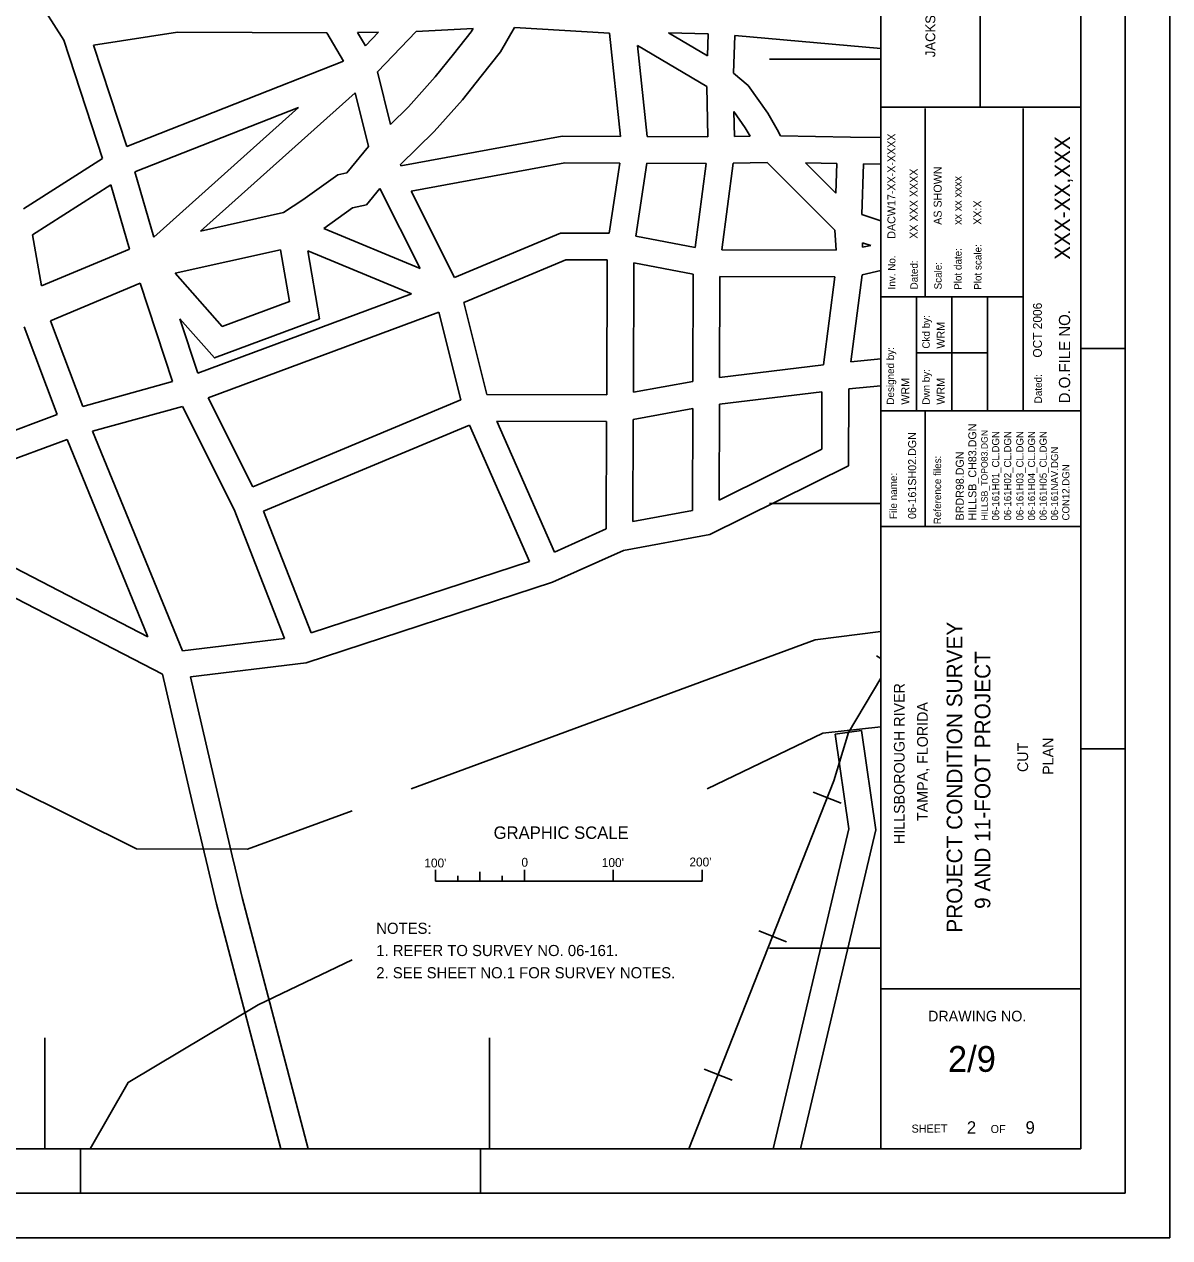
# Model space of a CAD drawing. Extents: x 503330 to 511530, y 1310349 to 1316149.
# Drawn here: x 508954 to 511530, y 1310349 to 1313078 of the extents above; entities that cross this region are included whole.
import ezdxf

# ---------------------------------------------------------------- set-up
doc = ezdxf.new("R2010")
doc.units = 0
for name, color, linetype in [('G-ANNO-TEXT', 7, 'Continuous'), ('G-ANNO-TTLB', 7, 'Continuous'), ('Level 1', 7, 'Continuous'), ('Level 2', 7, 'Continuous'), ('Level 23', 7, 'Continuous'), ('Level 32', 7, 'Continuous'), ('Level 37', 7, 'Continuous'), ('Level 5', 7, 'Continuous'), ('Level 6', 7, 'Continuous')]:
    doc.layers.add(name, color=color, linetype=linetype)

msp = doc.modelspace()

# ---------------------------------------------------------------- linework, layer by layer
at = {"layer": 'G-ANNO-TTLB'}
for p, q in [((511430.3, 1310448.5), (511430.3, 1316048.5)), ((510880.3, 1310548.5), (510880.3, 1315948.5)), ((511330.3, 1315948.5), (511330.3, 1310548.5)), ((511103.7, 1313931.1), (511103.7, 1312891.3)), ((511330.3, 1312891.3), (510880.3, 1312891.3)), ((510979.9, 1312888.5), (510979.9, 1312464.7)), ((511200.7, 1312888.5), (511200.7, 1312208.5)), ((511200.7, 1312464.7), (510880.3, 1312464.7)), ((510960.5, 1312464.7), (510960.5, 1312208.5)), ((511040.3, 1312464.7), (511040.3, 1312208.5)), ((511120.7, 1312464.7), (511120.7, 1312208.5)), ((511430.3, 1312348.5), (511330.3, 1312348.5)), ((511120.7, 1312338.9), (510960.5, 1312338.9)), ((511330.3, 1312208.5), (510880.3, 1312208.5)), ((510979.9, 1312208.5), (510979.9, 1311948.3)), ((511330.3, 1311948.3), (510880.3, 1311948.3)), ((511430.3, 1311448.5), (511330.3, 1311448.5)), ((511330.3, 1310908.5), (510880.3, 1310908.5)), ((511330.3, 1310548.5), (503680.3, 1310548.5)), ((509080.3, 1310448.5), (509080.3, 1310548.5)), ((509980.3, 1310448.5), (509980.3, 1310548.5)), ((503430.3, 1310448.5), (511430.3, 1310448.5))]:
    msp.add_line(p, q, dxfattribs=at)
for points in [[(503330.3, 1310348.5), (511530.3, 1310348.5), (511530.3, 1316148.5), (503330.3, 1316148.5)], [(503330.3, 1310348.5), (511530.3, 1310348.5), (511530.3, 1316148.5), (503330.3, 1316148.5)], [(503330.3, 1316148.5), (511530.3, 1316148.5), (511530.3, 1310348.5), (503330.3, 1310348.5)]]:
    msp.add_lwpolyline(points, close=True, dxfattribs=at)
msp.add_lwpolyline([(511480.3, 1310348.5), (511530.3, 1310348.5), (511530.3, 1310398.5)], dxfattribs=at)
at = {"layer": 'Level 1'}
for p, q in [((509878.7, 1311150.9), (509878.7, 1311176)), ((509978.7, 1311150.9), (509978.7, 1311171.4)), ((510078.7, 1311150.9), (510078.7, 1311176)), ((510078.7, 1311150.9), (510078.7, 1311176)), ((510278.7, 1311150.9), (510278.7, 1311176)), ((510478.7, 1311150.9), (510478.7, 1311176)), ((509878.7, 1311150.9), (510478.7, 1311150.9)), ((509928.7, 1311151.4), (509928.7, 1311162.9)), ((509978.7, 1311151.4), (509978.7, 1311162.9)), ((510028.7, 1311151.4), (510028.7, 1311162.9)), ((510078.7, 1311150.9), (510078.7, 1311162.9))]:
    msp.add_line(p, q, dxfattribs=at)
at = {"layer": 'Level 2'}
for p, q in [((510630.3, 1313000), (510880.3, 1313000)), ((510630.3, 1312000), (510880.3, 1312000)), ((510630.3, 1311000), (510880.3, 1311000)), ((509000, 1310548.5), (509000, 1310798.5)), ((510000, 1310548.5), (510000, 1310798.5))]:
    msp.add_line(p, q, dxfattribs=at)
at = {"layer": 'Level 23'}
for p, q in [((509350.1, 1312613.1), (509536.7, 1312654.4)), ((508992.1, 1312489.6), (509190.3, 1312572.4)), ((509293.1, 1312518.5), (509530.1, 1312571)), ((509012.5, 1312411.4), (509214.2, 1312495.7))]:
    msp.add_line(p, q, dxfattribs=at)
for points in [[(509777.5, 1312852.8), (509817.7, 1312892.2), (509878.3, 1312959.9), (509919.1, 1313011.2), (509958.7, 1313060.9), (509963.2, 1313068.8)], [(509800.1, 1312763), (509875.6, 1312836.8), (509939.5, 1312908.3), (509981.7, 1312961.4), (510025.2, 1313016), (510056.3, 1313070.6)], [(509536.7, 1312654.4), (509580.4, 1312683.1), (509658.9, 1312739.5), (509679.4, 1312744.1), (509728, 1312802.9)], [(509627.4, 1312618.4), (509692.2, 1312665), (509723.5, 1312671.9), (509753.8, 1312708.5)]]:
    msp.add_lwpolyline(points, dxfattribs=at)
at = {"layer": 'Level 32'}
for p, q in [((508895.9, 1313275.2), (509042.6, 1313042.1)), ((509109.4, 1313030.8), (509298.3, 1313060.5)), ((509298.3, 1313060.5), (509634, 1313059.2)), ((509634, 1313059.2), (509671.7, 1312994.9)), ((509703.2, 1313059.9), (509750.7, 1313060.5)), ((509703.2, 1313059.9), (509721.1, 1313029.4)), ((509750.7, 1313060.5), (509721.1, 1313029.4)), ((509835.2, 1313062.1), (509748.4, 1312971.1)), ((509835.2, 1313062.1), (509963.2, 1313068.8)), ((510056.3, 1313070.6), (510269.8, 1313058.3)), ((510269.8, 1313058.3), (510294.7, 1312825.9)), ((510403.1, 1313058.6), (510490.3, 1313006.8)), ((510403.1, 1313058.6), (510491.9, 1313056.6)), ((510491.9, 1313056.6), (510490.3, 1313006.8)), ((509042.6, 1313042.1), (509129.9, 1312776.5)), ((509109.4, 1313030.8), (509184.3, 1312803.3)), ((510333.1, 1313030.4), (510355.1, 1312825.7)), ((510333.1, 1313030.4), (510488.9, 1312937.8)), ((510551.9, 1313053.2), (510549, 1312968.5)), ((510551.9, 1313053.2), (510880.3, 1313023.5)), ((509184.3, 1312803.3), (509671.7, 1312994.9)), ((509748.4, 1312971.1), (509777.5, 1312852.8)), ((509698.2, 1312924.2), (509350.1, 1312613.1)), ((509698.2, 1312924.2), (509728, 1312802.9)), ((510488.9, 1312937.8), (510491.2, 1312825.2)), ((509202.2, 1312745.9), (509570.7, 1312890.8)), ((509570.7, 1312890.8), (509244.9, 1312599.5)), ((510550.1, 1312881.7), (510551.2, 1312825.7)), ((510355.1, 1312825.7), (510491.2, 1312825.2)), ((510551.2, 1312825.7), (510586.8, 1312826.5)), ((510655.1, 1312827.2), (510812.5, 1312824)), ((510812.5, 1312824), (510880.3, 1312823.8)), ((508951.9, 1312662.9), (509129.9, 1312776.5)), ((509800.1, 1312763), (509800.9, 1312759.7)), ((510293.3, 1312765.9), (510269.3, 1312607.9)), ((510353.9, 1312765.7), (510329, 1312601.8)), ((510353.9, 1312765.7), (510487.7, 1312765.2)), ((510487.7, 1312765.2), (510463, 1312576.2)), ((510548.3, 1312765.7), (510522.8, 1312570.6)), ((510548.3, 1312765.7), (510624.7, 1312767.3)), ((510624.7, 1312767.3), (510777.3, 1312615.2)), ((510710.9, 1312766.1), (510779.1, 1312698.1)), ((510710.9, 1312766.1), (510781.4, 1312764.7)), ((510781.4, 1312764.7), (510779.1, 1312698.1)), ((510841.4, 1312763.9), (510837.4, 1312650)), ((510841.4, 1312763.9), (510880.3, 1312763.8)), ((509202.2, 1312745.9), (509244.9, 1312599.5)), ((508972.1, 1312604.6), (509148.1, 1312717)), ((509148.1, 1312717), (509190.3, 1312572.4)), ((509753.8, 1312708.5), (509844.2, 1312528.7)), ((509823.8, 1312702.9), (509921.4, 1312508.6)), ((510837.4, 1312650), (510880.3, 1312636.3)), ((509627.4, 1312618.4), (509844.2, 1312528.7)), ((508972.1, 1312604.6), (508992.1, 1312489.6)), ((510329, 1312601.8), (510463, 1312576.2)), ((510777.3, 1312615.2), (510779.8, 1312569.7)), ((509591.5, 1312568.3), (509825.1, 1312471.7)), ((510522.8, 1312570.6), (510779.8, 1312569.7)), ((510839, 1312586.5), (510839.5, 1312576.5)), ((510839, 1312586.5), (510857.8, 1312580.5)), ((510839.5, 1312576.5), (510857.8, 1312580.5)), ((510264.9, 1312547.9), (510263.8, 1312244.4)), ((510324.9, 1312541.5), (510323.8, 1312250.3)), ((510324.9, 1312541.5), (510458.5, 1312516)), ((510458.5, 1312516), (510457.6, 1312274.9)), ((510518.5, 1312510.6), (510517.7, 1312283.8)), ((510518.5, 1312510.6), (510777.3, 1312509.7)), ((510777.3, 1312509.7), (510751.5, 1312312.2)), ((510838.5, 1312514.8), (510812.9, 1312318.7)), ((510838.5, 1312514.8), (510880.3, 1312524.1)), ((509214.2, 1312495.7), (509286.9, 1312274.7)), ((509344, 1312293.2), (509825.1, 1312471.7)), ((509367.1, 1312237.7), (509886.2, 1312430.4)), ((509886.2, 1312430.4), (509935.5, 1312233.2)), ((509942.5, 1312452.4), (509994.3, 1312245.4)), ((509012.5, 1312411.4), (509085.1, 1312218.7)), ((509303.6, 1312415.9), (509344, 1312293.2)), ((508953.7, 1312397.4), (509028, 1312200.1)), ((510812.9, 1312318.7), (510880.3, 1312325.4)), ((510517.7, 1312283.8), (510751.5, 1312312.2)), ((509085.1, 1312218.7), (509286.9, 1312274.7)), ((510323.8, 1312250.3), (510457.6, 1312274.9)), ((510808.2, 1312258), (510880.3, 1312265.1)), ((509367.1, 1312237.7), (509467.7, 1312037.7)), ((509994.3, 1312245.4), (510263.8, 1312244.4)), ((510517.5, 1312223.3), (510748.1, 1312251.3)), ((510748.1, 1312251.3), (510747.7, 1312122.1)), ((510808.2, 1312258), (510807.5, 1312084.8)), ((509107.2, 1312162.6), (509309.5, 1312218.7)), ((509309.5, 1312218.7), (509426, 1311987)), ((509467.7, 1312037.7), (509935.5, 1312233.2)), ((510323.6, 1312189.3), (510457.4, 1312213.9)), ((510457.4, 1312213.9), (510456.6, 1311984.1)), ((510517.5, 1312223.3), (510516.7, 1312007.5)), ((508799, 1312115.1), (509028, 1312200.1)), ((510016.9, 1312185.3), (510146.2, 1311891)), ((510016.9, 1312185.3), (510263.6, 1312184.4)), ((510263.6, 1312184.4), (510262.7, 1311942.9)), ((510323.6, 1312189.3), (510322.8, 1311959.5)), ((509107.2, 1312162.6), (509309.7, 1311668.8)), ((509492, 1311982.8), (509955.2, 1312176.4)), ((509955.2, 1312176.4), (510090.1, 1311869.5)), ((508786.1, 1312046.3), (509049.9, 1312144.2)), ((509049.9, 1312144.2), (509231.9, 1311700.4)), ((510516.7, 1312007.5), (510747.7, 1312122.1)), ((510496, 1311930.3), (510807.5, 1312084.8)), ((508655.8, 1311998), (509231.9, 1311700.4)), ((508577, 1311971.1), (509264.6, 1311616)), ((509426, 1311987), (509539.3, 1311696.7)), ((509492, 1311982.9), (509599, 1311708.9)), ((510322.8, 1311959.5), (510456.6, 1311984.1)), ((510146.2, 1311891), (510262.7, 1311942.9)), ((510301.6, 1311894.6), (510496, 1311930.3)), ((510141.7, 1311823.3), (510301.6, 1311894.6)), ((509599, 1311708.9), (510090.1, 1311869.5)), ((509587.9, 1311642.1), (510141.7, 1311823.3)), ((509309.7, 1311668.8), (509539.3, 1311696.7)), ((509327.5, 1311610.5), (509587.9, 1311642.1)), ((509331, 1311332.2), (509264.6, 1311616)), ((509389.4, 1311345.8), (509327.5, 1311610.5)), ((510837.3, 1311489.5), (510777.9, 1311481)), ((509424.7, 1311195.2), (509389.4, 1311345.8)), ((509366.3, 1311181.5), (509331, 1311332.2)), ((509385.8, 1311099.2), (509366.3, 1311181.4)), ((509444, 1311113.8), (509424.7, 1311195.3)), ((509530.5, 1310548.5), (509385.8, 1311099.2)), ((509592.5, 1310548.5), (509444, 1311113.8))]:
    msp.add_line(p, q, dxfattribs=at)
for points in [[(510549, 1312968.5), (510582.1, 1312940.4), (510626.1, 1312878), (510647.6, 1312841.3), (510655.1, 1312827.2)], [(510550.1, 1312881.7), (510575.6, 1312845.4), (510586.8, 1312826.5)], [(509800.9, 1312759.7), (510164, 1312826.4), (510294.7, 1312825.9)], [(509823.8, 1312702.9), (510169.4, 1312766.4), (510293.3, 1312765.9)], [(509921.4, 1312508.6), (510159.9, 1312608.3), (510269.3, 1312607.9)], [(509530.1, 1312571), (509550.4, 1312454.5), (509399.1, 1312398.3), (509293.1, 1312518.5)], [(509591.5, 1312568.3), (509618, 1312415.6), (509381.3, 1312327.7), (509303.6, 1312415.9)], [(509942.5, 1312452.4), (510171.9, 1312548.3), (510264.9, 1312547.9)], [(510777.9, 1311481), (510808.6, 1311268.4), (510638.2, 1310548.5)], [(510837.3, 1311489.5), (510869.6, 1311265.7), (510699.8, 1310548.5)]]:
    msp.add_lwpolyline(points, dxfattribs=at)
at = {"layer": 'Level 37'}
for p, q in [((510871.1, 1311657.3), (510880.3, 1311651.7)), ((510728.6, 1311350.6), (510791.3, 1311325.9)), ((510605.9, 1311039), (510668.5, 1311014.4)), ((510483.2, 1310727.5), (510545.8, 1310702.8))]:
    msp.add_line(p, q, dxfattribs=at)
msp.add_lwpolyline([(510880.3, 1311607), (510807.6, 1311485.3), (510774.9, 1311376.3), (510448.9, 1310548.5)], dxfattribs=at)
at = {"layer": 'Level 5'}
for points in [[(508324.1, 1311750.7), (508382.1, 1311658.9), (508498.5, 1311575.2), (509205.9, 1311223), (509455.9, 1311222.3), (509691.3, 1311309.1)], [(509824.3, 1311358.2), (510732.5, 1311693.5), (510880.3, 1311712.3)], [(510880.3, 1311498), (510749.7, 1311483.3), (510489.8, 1311358.2)], [(509691.3, 1310973.9), (509479.9, 1310872.2), (509187.7, 1310698), (509101.7, 1310548.5)]]:
    msp.add_lwpolyline(points, dxfattribs=at)

# ---------------------------------------------------------------- texts
at = {"layer": 'G-ANNO-TEXT'}
for s, height, rotation, p in [('JACKSONVILLE DISTRICT,  CORPS OF ENGINEERS', 21.998, 90, (511002.9, 1313004.1)), ('Plot date:', 16.6, 90, (511062.1, 1312480.9)), ('Plot scale: ', 16.6, 90, (511106.9, 1312480.9)), ('Inv. No.', 16.6, 90, (510913.3, 1312481.7)), ('Dated:', 16.6, 90, (510963.5, 1312481.7)), ('Scale:', 16.6, 90, (511017.3, 1312481.7)), ('D.O.FILE NO.', 25.2, 90, (511306.3, 1312225.5)), ('Ckd by:', 16.6, 90, (510990.5, 1312348.5)), ('Designed by:', 16.6, 90, (510910.3, 1312222.5)), ('Dwn by:', 16.6, 90, (510990.5, 1312222.5)), ('Dated:', 16.6, 90, (511242.7, 1312225.5)), ('Reference files:', 16.6, 90.0009, (511016.1, 1311953.5)), ('File name:', 16.6, 90.0009, (510916.9, 1311965.3))]:
    msp.add_text(s, height=height, rotation=rotation, dxfattribs=at).set_placement(p)
msp.add_text('DRAWING NO.', height=24, dxfattribs=at).set_placement((510986.7, 1310835.1))
at = {"layer": 'Level 1'}
for s, height, p in [('GRAPHIC SCALE', 28, (510009.5, 1311245.7)), ("100'", 20, (509853.6, 1311181.5)), ('0', 20, (510072, 1311183.1)), ("100'", 20, (510252.8, 1311182.4)), ("200'", 20, (510449.8, 1311183.7)), ('NOTES:', 25, (509745.5, 1311032.1)), ('1. REFER TO SURVEY NO. 06-161.', 25, (509745.5, 1310982.1)), ('2. SEE SHEET NO.1 FOR SURVEY NOTES.', 25, (509745.5, 1310932.1))]:
    msp.add_text(s, height=height, dxfattribs=at).set_placement(p)
at = {"layer": 'Level 5'}
for s, height, rotation, p in [('AS SHOWN', 18, 90.0009, (511017.3, 1312627.1)), ('xx xx xxxx', 18, 90.0009, (511062.1, 1312627.1)), ('XX:X', 18, 90.0009, (511106.9, 1312627.1)), ('WRM', 18, 90.001, (511024.3, 1312348.5)), ('WRM', 18, 90.001, (510944.5, 1312222.5)), ('WRM', 18, 90.001, (511024.3, 1312222.5)), ('06-161SH02.DGN', 18, 90.0009, (510959.9, 1311965.3)), ('HILLSB_CH83.DGN', 18, 90.0009, (511095.3, 1311961.9)), ('HILLSB_TOPO83.DGN', 14.58, 90.0009, (511120.8, 1311961.9)), ('06-161H01_CL.DGN', 16.2, 90.0009, (511146.8, 1311961.9)), ('06-161H02_CL.DGN', 16.2, 90.0009, (511173.7, 1311961.9)), ('06-161H03_CL.DGN', 16.2, 90.0009, (511201.3, 1311961.9)), ('06-161H04_CL.DGN', 16.2, 90.0009, (511227.5, 1311961.9)), ('06-161H05_CL.DGN', 16.2, 90.0009, (511253.6, 1311961.9)), ('06-161NAV.DGN', 16.2, 90.0009, (511279.3, 1311961.9)), ('CON12.DGN', 16.2, 90.0009, (511304.7, 1311961.9)), ('SHEET', 18.1, 0.34, (510949.7, 1310584.9))]:
    msp.add_text(s, height=height, rotation=rotation, dxfattribs=at).set_placement(p)
for s, height, p in [('2/9', 58, (511031.5, 1310721.7)), ('2', 28, (511074, 1310582.5)), ('OF', 18.11, (511127.5, 1310584.1)), ('9', 28, (511206, 1310582.5))]:
    msp.add_text(s, height=height, dxfattribs=at).set_placement(p)
at = {"layer": 'Level 6'}
for s, height, rotation, p in [('DACW17-XX-X-XXXX', 17.999, 90.0009, (510913.3, 1312595.7)), ('XXX-XX,XXX', 35, 90, (511306.3, 1312548.3)), ('XX XXX XXXX', 17.999, 90.0009, (510963.5, 1312595.7)), ('OCT 2006', 20, 90, (511242.7, 1312328.3)), ('BRDR98.DGN', 18, 90.0009, (511067.1, 1311961.9)), ('PROJECT CONDITION SURVEY', 35, 90, (511063.6, 1311034.6)), ('9 AND 11-FOOT PROJECT', 35, 90, (511126.8, 1311088.1)), ('HILLSBOROUGH RIVER', 24, 90, (510934, 1311234.1)), ('TAMPA, FLORIDA', 24, 90, (510986.2, 1311286)), ('PLAN', 24, 90, (511268.7, 1311389.7)), ('CUT', 24, 90, (511211.7, 1311396.1))]:
    msp.add_text(s, height=height, rotation=rotation, dxfattribs=at).set_placement(p)

doc.saveas('drawing.dxf')
